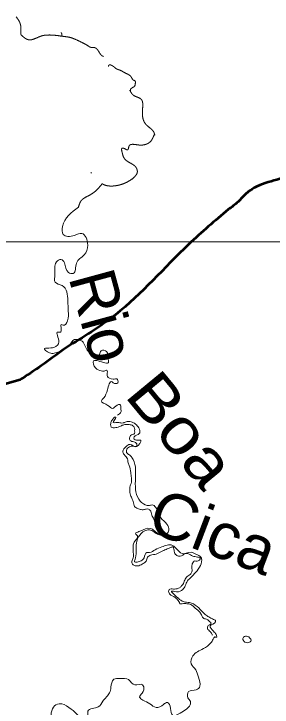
# Model space of a CAD drawing. Extents: x 512883 to 1063249, y 8784064 to 9081064.
# Drawn here: x 755485 to 763916, y 8877393 to 8900031 of the extents above; entities that cross this region are included whole.
import ezdxf

# ---------------------------------------------------------------- set-up
doc = ezdxf.new("R2010")
doc.units = 0
doc.header["$LTSCALE"] = 600
doc.linetypes.add('DOT_DASHED', pattern=[7.7, 5, -1.2, 0.3, -1.2])
for name, color, linetype, lineweight in [('1', 7, 'Continuous', 25), ('10', 7, 'Continuous', 53), ('4', 7, 'Continuous', 13), ('60', 7, 'Continuous', 25), ('7', 7, 'Continuous', 13)]:
    doc.layers.add(name, color=color, linetype=linetype, lineweight=lineweight)

msp = doc.modelspace()

# ---------------------------------------------------------------- linework, layer by layer
at = {"layer": '1', "lineweight": 13}
msp.add_line((581090.6, 8892594.3), (934660.9, 8892579.8), dxfattribs=at)
at = {"layer": '10'}
for points in [[(763702, 8912466.9), (764825.3, 8911589.2), (765720.4, 8910819.5), (766157.6, 8909758.6), (766553.1, 8908968.2), (767073.5, 8908302.5), (767198.5, 8907740.9), (767614.8, 8906617.6), (767698.1, 8905327.9), (767885.4, 8904225.4), (768052, 8903185.4), (767927.1, 8902228.5), (767677.2, 8901625.3), (767510.7, 8900938.8), (767552.3, 8900148.4), (768280.9, 8899233.1), (769051.2, 8898754.7)], [(768831.1, 8898395.2), (768162.8, 8896996.2), (767837.2, 8896640.4), (767480.9, 8896086.4), (767150.1, 8895613.7), (766692.1, 8895273.2), (766030.5, 8895334.2), (765272.3, 8895252.9), (764814.2, 8894907.2), (764071.2, 8894612.4), (763333.3, 8894348.2), (763058.5, 8894155), (762804.1, 8893895.8), (762483.5, 8893641.7)], [(762483.5, 8893641.7), (761195.1, 8892507.8), (758797.5, 8890203.4), (757198.2, 8889136.4)], [(757198.2, 8889136.4), (755746, 8888119.4), (755690.2, 8888084)], [(755690.2, 8888084), (752119.9, 8885734.8), (752219, 8885133.7), (752040.6, 8884432.4), (750792.3, 8884272.1), (750079, 8884512.5), (749385.4, 8884612.7), (748454.1, 8884592.7), (747879.5, 8884211.9), (746651, 8883370.3), (746016.9, 8882528.7), (745382.8, 8881446.7), (744867.7, 8880645.1)]]:
    msp.add_spline(points, degree=3, dxfattribs=at)
at = {"layer": '4', "linetype": 'DOT_DASHED'}
msp.add_line((758022.3, 8894834.1), (758000, 8894851.3), dxfattribs=at)
at = {"layer": '4'}
msp.add_line((762956.5, 8879602.1), (762956.5, 8879591.9), dxfattribs=at)
msp.add_line((762956.5, 8879602.1), (762956.5, 8879591.9), dxfattribs=at)
at = {"layer": '4', "linetype": 'DOT_DASHED'}
for points in [[(755709.9, 8899354), (755674.5, 8899758.1), (755562.2, 8899929)], [(757046.1, 8899303.2), (757041, 8899400.1), (757025.6, 8899425.8)], [(755709.9, 8899354), (755965.9, 8899184.8), (756416.4, 8899318.1), (756559.7, 8899338.6), (756897.6, 8899323.2), (757122.9, 8899292.5), (757296.9, 8899266.8), (757512, 8899189.9), (757727, 8899087.4), (757885.7, 8899000.2), (758013.7, 8898933.6), (758121.2, 8898928.4), (758264.5, 8898784.9), (758351.5, 8898672.1), (758622.9, 8898559.3), (758702.7, 8898498.7)], [(759290.8, 8897508.7), (759292.6, 8897565.4), (759338.4, 8897611.2), (759430, 8897677.3), (759450.4, 8897763.7), (759440.2, 8897839.9), (759363.9, 8897885.6), (759353.7, 8897900.9), (759302.8, 8897987.3), (759165.4, 8898078.8), (759084, 8898119.4), (759007.6, 8898165.2), (758936.4, 8898195.7), (758834.6, 8898236.3), (758722.7, 8898322.7), (758585.2, 8898353.2), (758570.6, 8898316.4)], [(759269.1, 8897538.7), (759389.3, 8897372.3), (759648.8, 8897235.1), (759689.6, 8896970.8), (759694.7, 8896635.3), (759786.3, 8896432), (760050.9, 8896172.8), (760086.7, 8896073.5)], [(760074.1, 8896108.6), (759923.7, 8895842.4), (759659, 8895745.9), (759430, 8895766.2), (759251.9, 8895725.5), (759201, 8895588.3), (759078.9, 8895639.1), (759017.8, 8895644.2), (759017.8, 8895512.1), (759094.2, 8895303.7), (759292.6, 8895156.3), (759450.4, 8895044.5), (759516.5, 8894881.8), (759369, 8894653.1)], [(757592.9, 8893717.9), (757699.8, 8893951.7), (757908.4, 8894083.9), (758152.7, 8894246.5), (758346.1, 8894460), (758365.7, 8894487.6)], [(759369, 8894653.1), (759155.2, 8894526.1), (758773.5, 8894414.2), (758376.6, 8894480.3), (758365.7, 8894487.6)]]:
    msp.add_spline(points, degree=3, dxfattribs=at)
at = {"layer": '4'}
for points in [[(757592.9, 8893717.9), (757074.2, 8893087.4), (757094.6, 8892828.2), (757462.9, 8892797.7), (757703.3, 8892863.8), (757897.7, 8892482.7), (757780.1, 8892157.5), (757529.4, 8891893.3), (757422, 8891552.9), (757263.4, 8891588.4), (757135.6, 8891903.5), (757023, 8892015.2), (756874.7, 8891928.9), (756823.5, 8891522.4), (756833.8, 8891268.3), (757063.9, 8891156.5), (757248.1, 8890668.8), (757258.3, 8890318.2), (757237.8, 8890008.2), (757089.5, 8889860.9), (757033.2, 8889886.3), (757012.8, 8889642.4), (756925.8, 8889642.4), (756956.5, 8889317.2), (756808.2, 8889144.4), (756562.7, 8889119), (756485.9, 8889108.8), (756644.5, 8888961.5), (756803.1, 8888946.3), (757110, 8889078.4), (757314.6, 8889225.7), (757411.8, 8889362.9), (757672.6, 8889368), (757882.3, 8889053), (758035.8, 8888931), (758276.2, 8888910.7), (758337.6, 8889027.6), (758511.5, 8889007.2), (758552.4, 8888788.7), (758578, 8888651.6), (758235.3, 8888697.3), (758087, 8888697.3), (758148.3, 8888473.7), (758337.6, 8888372.1), (758429.7, 8888367), (758521.7, 8888392.4), (758532, 8888260.3), (758537.1, 8888194.2), (758721.2, 8888102.8), (758762.2, 8888102.8), (758844, 8888113), (758874.7, 8887985.9), (758726.3, 8887985.9), (758690.5, 8888016.4), (758537.1, 8887752.2), (758419.4, 8887493.1), (758342.7, 8887396.5), (758557.5, 8887244.1), (758705.9, 8887142.5), (758854.2, 8887254.2), (758946.3, 8887274.6), (758977, 8887142.5), (758977, 8887025.6), (758869.6, 8886929.1)], [(758741.7, 8886827.4), (758675.2, 8886741.1), (758644.5, 8886619.1), (758659.8, 8886537.8), (758731.5, 8886517.5), (758884.9, 8886537.8), (758997.4, 8886583.6), (759104.9, 8886619.1), (759217.4, 8886619.1), (759345.3, 8886598.8), (759427.1, 8886497.2), (759427.1, 8886410.8), (759427.1, 8886329.5), (759289, 8886263.4), (759268.5, 8886207.5), (759258.3, 8886161.8), (759304.3, 8886085.6), (759437.3, 8886044.9), (759503.8, 8885968.7), (759488.5, 8885902.7), (759329.9, 8885953.5), (759237.8, 8885963.7), (759120.2, 8885872.2), (759063.9, 8885806.1), (759043.5, 8885750.2), (759084.4, 8885638.5), (759191.8, 8885501.3), (759207.2, 8885404.7), (759253.2, 8885282.8), (759299.2, 8885054.1), (759319.7, 8884876.3), (759319.7, 8884734), (759273.7, 8884576.5), (759268.5, 8884480), (759294.1, 8884317.4), (759350.4, 8884180.2), (759396.4, 8884022.7), (759427.1, 8883946.4), (759468, 8883910.9), (759585.7, 8883855), (759703.3, 8883839.8), (759805.6, 8883860.1), (759882.3, 8883860.1), (759928.4, 8883824.5), (759989.8, 8883661.9), (760056.3, 8883529.8), (760122.8, 8883402.8), (760204.6, 8883321.5), (760291.6, 8883209.7), (760342.7, 8883092.8), (760347.8, 8883062.3), (760148.3, 8883087.8), (760010.2, 8883199), (759936.9, 8883229.6), (759631.7, 8883153.8), (759493.6, 8883092.8), (759452.7, 8883067.4), (759503.8, 8883011.5), (759514.1, 8882920.1), (759452.7, 8882833.7), (759391.3, 8882727), (759376, 8882589.8), (759381.1, 8882447.5), (759381.1, 8882269.7), (759340.2, 8882152.8), (759340.2, 8882102), (759401.5, 8882025.8), (759565.2, 8882010.6), (759703.3, 8882081.7), (759805.6, 8882163), (759851.7, 8882284.9), (759948.8, 8882351), (760127.9, 8882391.6), (760306.9, 8882472.9), (760455.2, 8882544.1), (760532, 8882574.6), (760629.2, 8882615.2), (760649.6, 8882625.4), (760675.2, 8882630.4), (760700.8, 8882589.8), (760726.3, 8882447.5), (760762.2, 8882381.5), (760859.3, 8882325.6), (760956.5, 8882330.7), (761038.4, 8882386.6), (761161.1, 8882406.9), (761324.8, 8882325.6), (761478.3, 8882295.1), (761570.3, 8882254.4), (761539.6, 8882193.5), (761376, 8882168.1)], [(762107.4, 8879688.5), (762087, 8879769.8), (762000, 8879871.4), (761897.7, 8880044.2), (762066.5, 8880181.4), (762066.5, 8880222), (762030.7, 8880242.3), (761913, 8880303.3), (761790.3, 8880374.4), (761345.3, 8880765.7), (761222.5, 8880806.3), (761120.2, 8880816.5), (760977, 8880857.1), (760808.2, 8880989.2), (760629.2, 8881182.3), (760792.8, 8881156.9), (760997.4, 8881238.2), (761079.3, 8881355.1), (761150.9, 8881512.6), (761268.5, 8881634.6), (761376, 8881746.3), (761616.4, 8882203.6), (761606.1, 8882259.5), (761478.3, 8882366.2), (761196.9, 8882447.5), (761023, 8882401.8), (760659.8, 8882676.2), (760312, 8882625.4), (760097.2, 8882533.9), (759913, 8882447.5), (759826.1, 8882442.4), (759734, 8882269.7), (759636.8, 8882173.2), (759427.1, 8882142.7), (759452.7, 8882264.6), (759483.4, 8882747.3), (759821, 8883174.1), (759948.8, 8883174.1), (760081.8, 8883097.9), (760209.7, 8883031.8), (760342.7, 8883001.4), (760470.6, 8883052.2), (760542.2, 8883169), (760480.8, 8883372.3), (760281.3, 8883575.5), (760173.9, 8883804.2), (760092.1, 8883941.4), (760030.7, 8883992.2), (759907.9, 8883976.9), (759774.9, 8883997.3), (759560.1, 8884180.2), (759340.2, 8885547), (759258.3, 8885628.3), (759166.2, 8885704.5), (759161.1, 8885775.7), (759263.4, 8885897.6), (759370.8, 8885917.9), (759483.4, 8885902.7), (759626.6, 8886105.9), (759483.4, 8886105.9), (759416.9, 8886141.5), (759411.8, 8886217.7), (759580.6, 8886324.4), (759595.9, 8886431.1), (759514.1, 8886583.6), (759391.3, 8886680.1), (759222.5, 8886720.7), (759089.5, 8886685.2), (759079.3, 8886680.1), (758946.3, 8886680.1), (758813.3, 8886685.2), (758726.3, 8886685.2), (758757, 8886756.3), (758803.1, 8886822.4), (758818.4, 8886857.9)], [(758741.7, 8886827.4), (758767.3, 8886857.9), (758818.4, 8886857.9)], [(761376, 8882168.1), (761345.3, 8882132.5), (761309.5, 8882071.5), (761294.1, 8881954.7), (761294.1, 8881807.3), (761243, 8881726), (761115.1, 8881634.6), (761048.6, 8881502.4), (760977, 8881370.3), (760910.5, 8881304.3), (760813.3, 8881258.6), (760726.3, 8881248.4), (760654.7, 8881253.5), (760578, 8881248.4), (760542.2, 8881202.7), (760567.8, 8881090.9), (760751.9, 8880974), (760844, 8880872.4), (760890, 8880806.3), (760905.4, 8880770.8), (760982.1, 8880770.8), (761130.4, 8880770.8), (761258.3, 8880745.4), (761401.5, 8880623.4), (761560.1, 8880491.3), (761621.5, 8880379.5), (761682.9, 8880288.1), (761795.4, 8880257.6), (761887.5, 8880181.4), (761928.4, 8880135.6), (761892.6, 8880095), (761815.9, 8880039.1), (761805.6, 8879962.9), (761902.8, 8879851.1), (761954, 8879769.8), (761969.3, 8879739.3)], [(762956.5, 8879591.9), (762977, 8879673.2), (763048.6, 8879713.9), (763181.6, 8879658), (763232.7, 8879571.6), (763140.7, 8879500.5), (763063.9, 8879500.5), (762997.4, 8879546.2), (762956.5, 8879602.1)], [(762956.5, 8879591.9), (762977, 8879673.2), (763048.6, 8879713.9), (763181.6, 8879658), (763232.7, 8879571.6), (763140.7, 8879500.5), (763063.9, 8879500.5), (762997.4, 8879546.2), (762956.5, 8879602.1)], [(756792.8, 8875898), (756792.8, 8876162.2), (756654.7, 8876360.4), (756659.8, 8876665.2), (756700.8, 8876939.6), (756700.8, 8877142.9), (756777.5, 8877396.9), (756961.6, 8877503.6), (757283.9, 8877381.7), (757539.6, 8877168.3), (757749.4, 8877036.2), (757882.3, 8877097.1), (757902.8, 8877259.7), (758240.4, 8877402), (758388.8, 8877584.9), (758608.7, 8877864.4), (758654.7, 8878042.2), (758746.8, 8878301.3), (758951.4, 8878331.8), (759227.6, 8878291.2), (759437.3, 8878118.4), (759688, 8878118.4), (759723.8, 8878057.5), (759672.6, 8877854.2), (759590.8, 8877717), (759693.1, 8877625.6), (759923.3, 8877498.5), (760127.9, 8877381.7), (760373.4, 8877483.3), (760496.2, 8877544.3), (760598.5, 8877351.2), (760665, 8877132.7), (760915.6, 8877193.7), (761115.1, 8877325.8), (761243, 8877468.1), (761248.1, 8877579.8), (761166.2, 8877696.7), (761186.7, 8877899.9), (761432.2, 8877955.8), (761560.1, 8878077.8), (761509, 8878372.5), (761422, 8878611.3), (761273.7, 8878809.5), (761324.8, 8879063.5), (761672.6, 8879302.3), (761913, 8879490.3), (761989.8, 8879612.3), (762046, 8879703.7)], [(762026.5, 8879672), (762081.8, 8879678.3), (762107.4, 8879688.5)]]:
    msp.add_spline(points, degree=3, dxfattribs=at)

# ---------------------------------------------------------------- texts
at = {"layer": '60'}
msp.add_text('Rio', height=1500, rotation=285.269, dxfattribs=at).set_placement((757263.1, 8891430.5))
for s, rotation, width, p in [('Boa ', 309.544, 1.15, (759066.3, 8887562)), ('Cica', 339.142, 1.05, (759766.2, 8883172.6))]:
    msp.add_text(s, height=1500, rotation=rotation, dxfattribs=dict(at, width=width)).set_placement(p)
at = {"layer": '7'}
msp.add_text('Rio', height=1500, rotation=285.269, dxfattribs=at).set_placement((757263.1, 8891430.5))
for s, rotation, width, p in [('Boa ', 309.544, 1.15, (759066.3, 8887562)), ('Cica', 339.142, 1.05, (759766.2, 8883172.6))]:
    msp.add_text(s, height=1500, rotation=rotation, dxfattribs=dict(at, width=width)).set_placement(p)

doc.saveas('drawing.dxf')
